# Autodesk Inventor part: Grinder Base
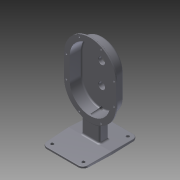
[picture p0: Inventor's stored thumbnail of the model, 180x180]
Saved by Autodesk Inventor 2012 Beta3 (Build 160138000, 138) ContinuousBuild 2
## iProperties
Created: 2010-12
Part Number: Grinder Base
Document SubType Name: Modeling
Designer: Thom Tremblay
Density: 7.25 g/cm^3
Material: Cast Iron
Mass: 1233.53 g
Surface Area: 883.619 cm^2
Volume: 170.142 cm^3
Author: Thom Tremblay
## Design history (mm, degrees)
sketch "Sketch1"
  geometry: L1 (-50, -50)-(-50, 0); L2 (50, 0)-(50, -50); L3 (-60, 0)-(-60, -50); L4 (60, -50)-(60, 0); A1 r 50 centre (0, 0) between (50, 0) and (-50, 0); A2 r 50 centre (0, -50) between (-50, -50) and (50, -50); A3 r 60 centre (0, -50) between (-60, -50) and (60, -50); A4 r 60 centre (0, 0) between (60, 0) and (-60, 0); 1 further point
  constraints: 8 end point, 8 point on circle, 4 centre point, 4 tangent, 2 parallel, 1 coincident, 1 vertical, 3 other
  dimensions: "d0" = 50 distance of L2.start L2.end; "d1" = 50 radius of A1; "d2" = 10 radial gap between concentric circles of A4 A1
extrude "Extrusion1" new body sketch "Sketch1" distance "d3" = 30; taper "d4" = -2 deg
fillet "Fillet1" dims "d7" = 6
shell "Shell3" dims "d132" = 3
extrude "Extrusion2" join sketch "Sketch1" distance "d5" = 4; taper "d6" = -2 deg
fillet "Fillet12" dims "d133" = 2
fillet "Fillet13" dims "d134" = 1
workplane "Work Plane2"
sketch "Sketch7"
  geometry: C1 r 7.5 at (0, -95); 1 further point
  constraints: 1 centre point, 1 vertical alignment
  dimensions: "d64" = 15 diameter of C1; "d65" = 95 distance of point (0, 0) C1.centre
extrude "Extrusion8" join sketch "Sketch7" stored distance "d66" = 12.7; taper "d67" = 2 deg
fillet "Fillet2" dims "d9" = 3, "d10" = 1
hole "Hole3" diameter "d70" = 8; stored, may be unused: countersink angle "d74" = 82 deg, drill point angle "d76" = 118 deg; dims "d68" = 10, "d69" = 10, "d71" = 9, "d72" = 9.525, "d73" = 6.35, "d75" = 30, "d77" = 0.62479, "d78" = 7.985
workplane "Work Plane1"
sketch "Sketch2"
  geometry: L1 (-20.917, -1.5)-(20.917, -1.5); L2 (20.917, -1.5)-(20.219, -21.5); L3 (20.219, -21.5)-(16.219, -21.5); L4 (16.219, -21.5)-(15.695, -6.5); L5 (15.695, -6.5)-(-15.695, -6.5); L6 (-15.695, -6.5)-(-16.219, -21.5); L7 (-16.219, -21.5)-(-20.219, -21.5); L8 (-20.219, -21.5)-(-20.917, -1.5); L9 (-16.219, -21.5)-(16.219, -21.5); 3 further points
  constraints: 18 end point, 3 parallel, 2 equal length, 2 midpoint, 2 vertical alignment, 1 collinear, 1 horizontal
  dimensions: "d12" = 4 deg angle of L8 L6; "d13" = 88 deg angle of L8 L1; "d14" = 1.5 distance from line of point (0, 0) L1; "d15" = 20 vertical distance of L1.end L2.end; "d16" = 4 distance of L2.end L3.end; "d17" = 5 distance between parallel lines of L1 L5
extrude "Extrusion3" join sketch "Sketch2" stored distance "d18" = 27.94; taper "d19" = 0 deg
sketch "Sketch3"
  geometry: L1 (-70, -150)-(70, -150) reference; L2 (-50, -150)-(50, -150); L3 (50, -150)-(50, -144); L4 (50, -144)-(-50, -144); L5 (-50, -144)-(-50, -150); 2 further points
  constraints: 8 end point, 2 parallel, 1 horizontal, 1 midpoint, 1 perpendicular, 1 point on line, 1 vertical alignment
  dimensions: "d20" = 100 distance of L3.end L4.end; "d21" = 6 distance of L2.end L3.end
extrude "Extrusion4" join sketch "Sketch3" distance "d22" = 63.5; taper "d23" = 0 deg
feature "FaceDraft1" dims angle "d24" = 2 deg
sketch "Sketch4"
  geometry: L1 (-50, -150)-(50, -150) reference; L2 (50, -150)-(50, -143.773) reference; L3 (50, -143.773)-(-50, -143.773) reference; L4 (-50, -143.773)-(-50, -150) reference; 1 further point
extrude "Extrusion5" join sketch "Sketch4" distance "d25" = 63.5; taper "d26" = 0 deg
feature "FaceDraft2" dims angle "d27" = 2 deg
fillet "Fillet3" dims "d28" = 12
fillet "Fillet4"
fillet "Fillet5"
fillet "Fillet6" dims "d29" = 4
fillet "Fillet7" dims "d30" = 4
fillet "Fillet8" dims "d31" = 2
sketch "Sketch5"
  geometry: C1 r 12.5 at (0, 0); 1 further point
  constraints: 1 centre point, 1 coincident
  dimensions: "d32" = 25 diameter of C1
extrude "Extrusion6" join sketch "Sketch5" distance "d33" = 5; taper "d35" = -2 deg; dims "d34" = 8, "d36" = -2 deg
hole "Hole1" diameter "d40" = 14; stored, may be unused: countersink angle "d44" = 82 deg, drill point angle "d46" = 118 deg; dims "d38" = 10, "d39" = 10, "d41" = 19.05, "d42" = 9.525, "d43" = 6.35, "d45" = 25.4
sketch "Sketch10"
  geometry: C1 r 12.5 at (0, -50); A1 r 60 centre (0, -50) between (-60, -50) and (-18.704, -107.01) reference; 1 further point
  constraints: 1 centre point, 1 coincident
  dimensions: "d135" = 25 diameter of C1
extrude "Extrusion9" join sketch "Sketch10" distance "d136" = 12; taper "d137" = -2 deg
fillet "Fillet9" dims "d37" = 3
hole "Hole2" diameter "d55" = 14; stored, may be unused: countersink angle "d59" = 82 deg, drill point angle "d61" = 118 deg; dims "d53" = 10, "d54" = 10, "d56" = 19.05, "d57" = 9.525, "d58" = 6.35, "d60" = 8
hole "Hole4" diameter "d81" = 7; stored, may be unused: countersink angle "d85" = 82 deg, drill point angle "d87" = 118 deg; dims "d79" = 10, "d80" = 10, "d82" = 12.7, "d83" = 12.8778, "d84" = 6.35, "d86" = 30.48
hole "Hole5" diameter "d90" = 7; stored, may be unused: countersink angle "d94" = 82 deg, drill point angle "d96" = 118 deg; dims "d88" = 10, "d89" = 10, "d91" = 12.7, "d92" = 12.8778, "d93" = 6.35, "d95" = 30.48
hole "Hole6" diameter "d99" = 7; stored, may be unused: countersink angle "d103" = 82 deg, drill point angle "d105" = 118 deg; dims "d97" = 10, "d98" = 10, "d100" = 12.7, "d101" = 12.8778, "d102" = 6.35, "d104" = 30.48
hole "Hole7" diameter "d108" = 7; stored, may be unused: countersink angle "d112" = 82 deg, drill point angle "d114" = 118 deg; dims "d106" = 10, "d107" = 10, "d109" = 12.7, "d110" = 12.8778, "d111" = 6.35, "d113" = 30.48
fillet "Fillet11" dims "d122" = 1
chamfer "Chamfer1" distance "d138" = 1; stored, may be unused: second distance "d139" = 2, angle "d140" = 45 deg
node "Hole11"
body "Solid1"
node "Projected Loop1"
sketch "Sketch11"
  geometry: 8 further points
hole "Hole10" sketch "Sketch11" diameter "d141" = 4.5; stored, may be unused: countersink angle "d145" = 90 deg, drill point angle "d147" = 0 deg; dims "d142" = 6, "d143" = 4, "d144" = 2, "d146" = 8
other parameters: "d63" = -35
